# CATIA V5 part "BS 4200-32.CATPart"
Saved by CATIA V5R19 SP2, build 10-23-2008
Part number: BS 4200-32
Bounding box of the stored display mesh (mm): x -47.487 to 47.487, y -47.487 to 47.487, z 0 to 129
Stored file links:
  C:\Users\Bora\Desktop\3D Katı model\BS serisi\BS 4200\BS 4200-32.CATPart
  C:\Program Files\Dassault Systemes\B19\intel_a\reffiles\standard\MetricThickPitch.txt
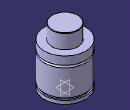
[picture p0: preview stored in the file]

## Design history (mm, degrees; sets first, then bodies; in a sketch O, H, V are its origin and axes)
Body1 (main body)
  Sketch1 on yz-plane, origin (0, 0, 0), H (0, 1, 0), V (0, 0, 1)
    point P2 (47.5, 72.5)
    point P5 (30, 128)
    point P7 (30, 128)
    point P11 (47.5, 77.5)
    point P13 (47.5, 77.5)
    point P14 (47.5, 72.5)
    line L1 (47.5, 13) -> (47.5, 72.5)
    line L2 (44.5, 13) -> (44.5, 8)
    line L3 (30, 128) -> (30, 96)
    arc A1 centre (29, 128) radius 1 from (30, 128) to (29, 129) ccw
    line L4 (47.5, 0) -> (47.5, 8)
    line L5 (47.5, 77.5) -> (47.5, 96)
    arc A2 centre (47.5, 75) radius 2.5 from (47.5, 77.5) to (47.5, 72.5) ccw
    line L6 (29, 129) -> (0, 129)
    point P15 (0, 129)
    line L7 (30, 96) -> (47.5, 96)
    line L8 (0, 0) -> (47.5, 0)
    line L9 (44.5, 13) -> (47.5, 13)
    line L10 (44.5, 8) -> (47.5, 8)
    coincidence: P15 V, P2 P14, P5 P7, P11 P13
    tangency: L6 A1
    horizontal: L7 H, L8 H, L9 H, L10 H
  Shaft1: profile Sketch1, axis Sketch1.V, angle 360
  Sketch2 on face of Shaft1 from Sketch1.L8, origin (0, 0, 0), H (1, 0, 0), V (0, -1, 0)
    point P1 (30, 0)
    distance P1 V = 30
  Hole1: placed by Sketch2, at (30, 0, 0) direction (0, 0, 1), diameter 6.647, depth 7, threaded "M8", thread diameter 8, thread depth 7, pitch 1.25
  CircPattern1: of Hole1, instances 4, angular step 90, axis from xy-plane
